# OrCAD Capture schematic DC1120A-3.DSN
size Custom; title: 50MHz to 3.8GHz DETECTOR; rev: 3; company: TM
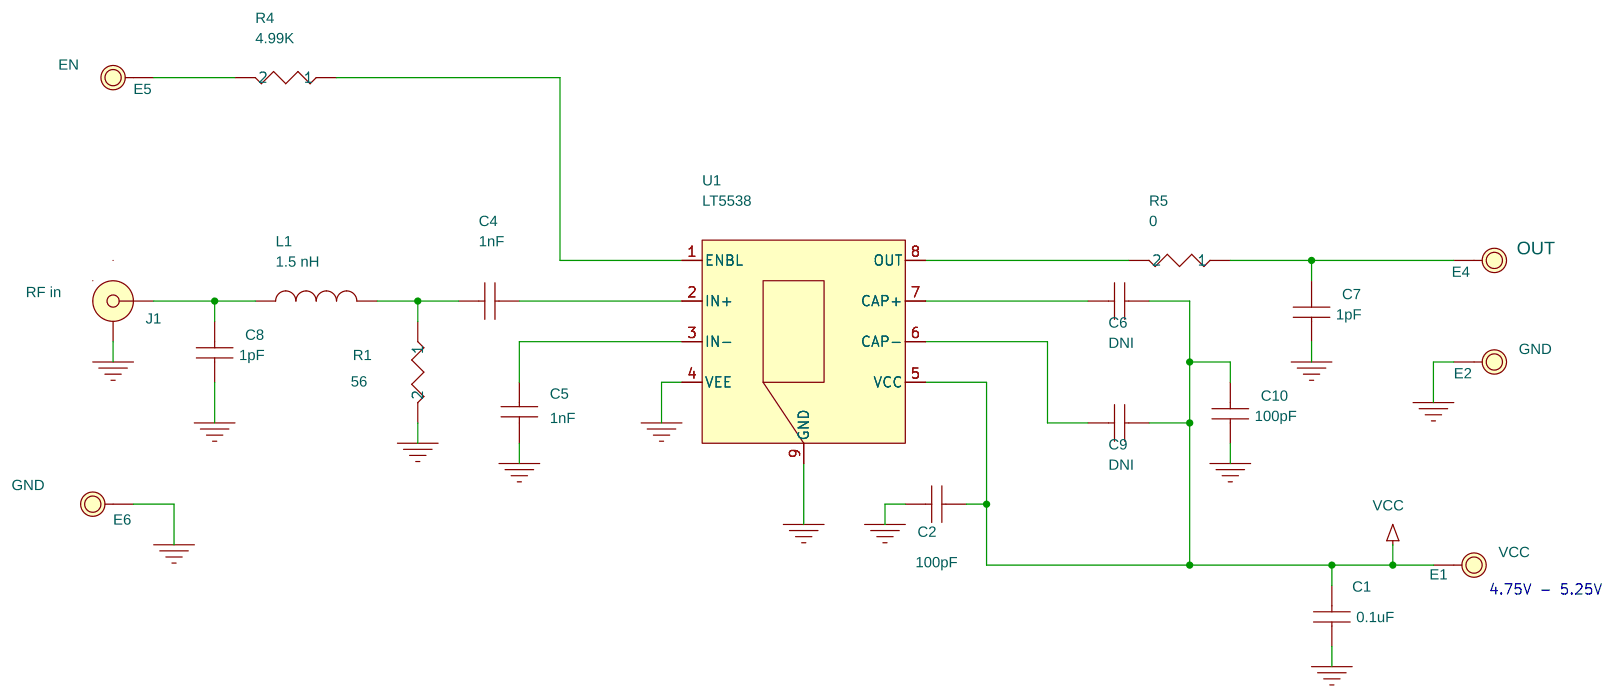
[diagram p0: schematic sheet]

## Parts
C1  0.1uF  [0603]
C2  100pF  [0402-RF]
C4  1nF  [0402-RF]
C5  1nF  [0402-RF]
C6  DNI  [0402-RF]
C7  1pF  [0402-RF]
C8  1pF  [0402-RF]
C9  DNI  [0402-RF]
C10  100pF  [0402-RF]
E1  VCC  [MILLMAX-2501-2]
E2  GND  [MILLMAX-2501-2]
E4  OUT  [MILLMAX-2501-2]
E5  EN  [MILLMAX-2501-2]
E6  GND  [MILLMAX-2501-2]
J1  RF in  [CON\SMA-END]
L1  1.5 nH  [0402]
R1  56  [0402-RF]
R4  4.99K  [0402-RF]
R5  0  [0402-RF]
U1  LT5538  [3x3DFN8]

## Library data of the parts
C1 C2 C4-C10 = CAP
E1 E2 E4-E6 = CON_KEY_575-4
J1 = CON_SMA-END
L1 = INDUCTOR
R1 = RES0402_0_1
R4 = RES0402_0
R5 = RES0402_0_2
U1 = LT5570_3

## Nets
GND: C1.1 C2.2 C5.2 C7.1 C8.1 C10.1 E2.1 E6.1 J1.2(SHIELD) J1.3(GND) J1.4(GND) J1.5(GND) R1.2 U1.4(VEE) U1.9(GND)
VCC: C1.2 C2.1 C6.1 C9.1 C10.2 E1.1 U1.5(VCC)
N857363: C9.2 U1.6(CAP-)
N858001: R4.1 U1.1(ENBL)
N860130: C4.1 U1.2(IN+)
N860194: C5.1 U1.3(IN-)
N863435: E5.1 R4.2
N866341: C6.2 U1.7(CAP+)
N871042: C4.2 L1.2 R1.1
N873971: C8.2 J1.1(CENTER) L1.1
N874192: R5.2 U1.8(OUT)
N874233: C7.2 E4.1 R5.1

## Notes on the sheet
- 4.75V - 5.25V
